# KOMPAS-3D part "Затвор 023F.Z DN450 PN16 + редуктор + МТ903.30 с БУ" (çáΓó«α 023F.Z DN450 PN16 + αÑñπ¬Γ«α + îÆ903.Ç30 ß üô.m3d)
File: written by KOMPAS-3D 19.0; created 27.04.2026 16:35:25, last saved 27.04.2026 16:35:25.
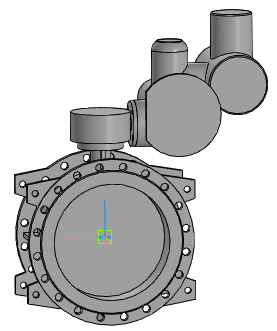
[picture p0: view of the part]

Document properties: Полное имя файла: ..\..\Затвор 023F.Z DN400-DN1600 + редуктор + МТ903\Затвор 023F.Z DN450 PN16 + редуктор + МТ903.А30 с БУ.a3d

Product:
- Part/product: Затвор 023F.Z DN450 PN16 + редуктор + МТ903.30 с БУ
    Масса: 537.988

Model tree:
1. Операция без истории:1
